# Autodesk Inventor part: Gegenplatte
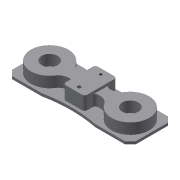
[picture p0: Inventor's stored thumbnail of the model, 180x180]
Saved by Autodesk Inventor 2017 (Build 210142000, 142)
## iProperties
Created: 2015-04
Part Number: Gegenplatte
Material: Generisch
Document SubType Name: Modeling
Designer: e_krauts
Density: 1 g/cm^3
Appearance: Vorgabe
Author: e_krauts
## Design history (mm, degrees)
sketch "Skizze1"
  geometry: L1 (0, 122.557)-(0, -117.957); L2 (-201.086, 0)-(208.971, 0); L3 (105, -40)-(-105, -40); L4 (-115, -30)-(-115, 30); L5 (-105, 40)-(105, 40); L6 (115, 30)-(115, -30); L7 (115, -40)-(-115, 40); L8 (-115, -40)-(115, 40); L9 (-115, 30)-(-105, 40); L10 (105, 40)-(115, 30); L11 (115, -30)-(105, -40); L12 (-105, -40)-(-115, -30); 2 further points
  constraints: 24 end point, 8 point on line, 2 midpoint, 2 parallel, 2 perpendicular, 1 coincident, 1 horizontal, 1 vertical
  dimensions: "d0" = 230 distance between parallel lines of L6 L4; "d1" = 80 distance between parallel lines of L3 L5; "d2" = 10 distance of L4.end L7.end; "d3" = 10 distance of L5.start L7.end (= d2); "d4" = 10 distance of L5.end L8.end (= d2); "d5" = 10 distance of L6.start L8.end (= d4); "d6" = 10 distance of L6.end L7.start (= d2); "d7" = 10 distance of L3.start L7.start (= d6); "d8" = 10 distance of L3.end L8.start (= d2); "d9" = 10 distance of L4.start L8.start (= d8)
extrude "Extrusion1" new body sketch "Skizze1" distance "d10" = 5; taper "d11" = 0 deg
sketch "Skizze2"
  geometry: L1 (-105, 40)-(105, 40) reference; L2 (0, 53.954)-(0, -63.401) reference; L3 (-137.09, 0)-(142.128, 0) reference; L4 (0, 10)-(-28.902, 10); L5 (0, -10)-(-28.902, -10); L6 (137.09, 0)-(-142.128, 0); L7 (0, -10)-(28.902, -10); L8 (0, 10)-(28.902, 10); A1 r 20 centre (-28.902, 30) between (-45.665, 19.091) and (-28.902, 10); A2 r 35 centre (-75, 0) between (-45.665, 19.091) and (-110, 0); A3 r 35 centre (-75, 0) between (-110, 0) and (-45.665, -19.091); A4 r 20 centre (-28.902, -30) between (-28.902, -10) and (-45.665, -19.091); A5 r 20 centre (28.902, 30) between (28.902, 10) and (45.665, 19.091); A6 r 20 centre (28.902, -30) between (45.665, -19.091) and (28.902, -10); A7 r 35 centre (75, 0) between (45.665, -19.091) and (110, 0); A8 r 35 centre (75, 0) between (110, 0) and (45.665, 19.091); 1 further point
  constraints: 16 point on circle, 14 end point, 14 symmetric about line, 8 centre point, 5 point on line, 2 perpendicular, 2 tangent, 1 horizontal, 1 parallel, 1 vertical, 6 other
  dimensions: "d18" = 20 diameter of L4 L3; "d19" = 150 diameter of A2.centre L2; "d20" = 20 radius of A1; "d21" = 35 radius of A2
extrude "Extrusion2" join sketch "Skizze2" distance "d22" = 20; taper "d23" = 0 deg; dims "d60" = 5, "d61" = 0
sketch "Skizze3"
  geometry: C1 r 15 at (-75, 0); C2 r 15 at (75, 0); A1 r 35 centre (-75, 0) between (-45.665, 19.091) and (-45.665, -19.091) reference; A2 r 35 centre (75, 0) between (45.665, -19.091) and (45.665, 19.091) reference; 1 further point
  constraints: 2 centre point, 2 coincident, 1 equal radius
  dimensions: "d24" = 30 diameter of C1
extrude "Extrusion3" cut sketch "Skizze3" stored distance "d25" = 20; taper "d26" = 0 deg
sketch "Skizze4"
  geometry: L1 (15, -30)-(-15, -30); L2 (-20, -25)-(-20, 25); L3 (-15, 30)-(15, 30); L4 (20, 25)-(20, -25); L5 (20, -30)-(-20, 30); L6 (-20, -30)-(20, 30); A1 r 5 centre (-15, 25) between (-15, 30) and (-20, 25); A2 r 5 centre (15, 25) between (20, 25) and (15, 30); A3 r 5 centre (15, -25) between (15, -30) and (20, -25); A4 r 5 centre (-15, -25) between (-20, -25) and (-15, -30); 1 further point
  constraints: 12 end point, 8 point on circle, 8 point on line, 8 tangent, 4 centre point, 3 equal radius, 2 midpoint, 2 parallel, 1 horizontal, 1 perpendicular
  dimensions: "d27" = 40 distance between parallel lines of L4 L2; "d28" = 60 distance between parallel lines of L1 L3; "d29" = 5 radius of A1
extrude "Extrusion4" join sketch "Skizze4" distance "d31" = 25; taper "d32" = 0 deg; dims "d65" = 5, "d66" = 0
sketch "Skizze8"
  geometry: L1 (-20, 25)-(-20, -25) reference; L2 (20, -25)-(20, 25) reference; L3 (-20, 0)-(20, 0); 3 further points
  constraints: 2 end point, 2 midpoint, 1 symmetric about line
hole "Bohrung2" sketch "Skizze8" diameter "d68" = 4.917; stored, may be unused: countersink angle "d72" = 90 deg, drill point angle "d74" = 118 deg; dims "d69" = 20, "d70" = 4, "d71" = 2, "d73" = 25
hole "Bohrung3" diameter "d77" = 6.6; stored, may be unused: countersink angle "d81" = 90 deg, drill point angle "d83" = 118 deg; dims "d75" = 20, "d76" = 20, "d78" = 20, "d79" = 11, "d80" = 6.4, "d82" = 25
sketch "Skizze9"
  geometry: L1 (105, 40)-(-105, 40) reference; L2 (115, -30)-(115, 30) reference; L3 (-49.749, 40)-(49.749, 40); L4 (0, 296.061)-(0, 191.763); L5 (-85.317, 0)-(97.839, 0); L6 (105, -40)-(-105, -40); A1 r 250 centre (0, 285) between (-49.749, 40) and (49.749, 40); A2 r 250 centre (0, -285) between (49.749, -40) and (-49.749, -40); 1 further point
  constraints: 8 end point, 4 point on circle, 4 point on line, 4 symmetric about line, 3 perpendicular, 2 centre point, 1 other
  dimensions: "d84" = 5 distance edge to line of A1 L3; "d85" = 250 radius of A1
extrude "Extrusion7" cut sketch "Skizze9" stored distance "d86" = 10; taper "d87" = 0 deg
fillet "Rundung6" dims "d88" = 5
fillet "Rundung7" dims "d89" = 30
node "Volumenkörper1"
